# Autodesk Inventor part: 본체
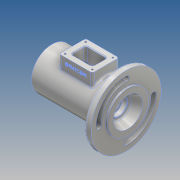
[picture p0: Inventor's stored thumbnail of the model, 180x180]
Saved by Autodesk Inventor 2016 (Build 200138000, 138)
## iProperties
Created: 2017-05
Part Number: 본체
Material: 알루미늄 6061
Document SubType Name: Modeling
Designer: Administrator
Mass: 680.072 g
Surface Area: 618.647 cm^2
Volume: 251.879 cm^3
Density: 2.7 g/cm^3
Appearance: 알루미늄 - 평지
Author: Administrator
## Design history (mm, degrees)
sketch "스케치1"
  geometry: L1 (57.5, 0)-(-57.5, 0); L2 (57.5, 0)-(57.5, 31); L3 (57.5, 31)-(-44.5, 31); L4 (-54.5, 31)-(-54.5, 53); L5 (-54.5, 53)-(-44.5, 53); L6 (-44.5, 53)-(-44.5, 31); L7 (-54.5, 31)-(-57.5, 31); L8 (-57.5, 31)-(-57.5, 0); 2 further points
  constraints: 16 end point, 5 perpendicular, 1 coincident, 1 horizontal, 1 midpoint, 1 point on line, 1 vertical
  dimensions: "d0" = 115 distance between parallel lines of L8 L2; "d2" = 62 diameter of L3 L1; "d4" = 13 distance between parallel lines of L8 L6; "d5" = 3 distance between parallel lines of L8 L4; "d6" = 106 diameter of L5 L1
revolve "회전1" sketch "스케치1" stored, may be unused: angle "d7" = 90 deg
sketch "스케치3"
  geometry: L1 (-57.5, 31)-(-57.5, -31) reference; L2 (57.5, 31)-(57.5, -31) reference; L3 (44.5, 31)-(-57.5, 31) reference; L4 (-26.5, -20)-(23.5, -20); L5 (23.5, -20)-(23.5, 20); L6 (23.5, 20)-(-26.5, 20); L7 (-26.5, 20)-(-26.5, -20); L8 (-26.5, -20)-(23.5, 20); L9 (23.5, -20)-(-26.5, 20); 3 further points
  constraints: 12 end point, 3 midpoint, 2 parallel, 1 horizontal, 1 horizontal alignment, 1 perpendicular
  dimensions: "d35" = 56 distance from line of point (-1.5, 0) L1; "d36" = 50 distance between parallel lines of L5 L7; "d37" = 40 distance between parallel lines of L4 L6
extrude "돌출1" join sketch "스케치3" distance "d38" = 44; taper "d39" = 0 deg
sketch "스케치2"
  geometry: L1 (57.5, 0)-(-57.5, 0); L2 (57.5, -31)-(57.5, 31) reference; L3 (-57.5, -31)-(-57.5, 31) reference; L4 (48.5, 0)-(48.5, 24); L5 (48.5, 24)-(45.5, 24); L6 (45.5, 24)-(45.5, 20); L7 (45.5, 20)-(36.5, 20); L8 (36.5, 20)-(36.5, 17.5); L9 (36.5, 17.5)-(33.25, 17.5); L10 (33.25, 17.5)-(33.25, 18.5); L11 (33.25, 18.5)-(31.5, 18.5); L12 (31.5, 18.5)-(31.5, 17.5); L13 (31.5, 17.5)-(20.5, 17.5); L14 (20.5, 17.5)-(20.5, 26); L15 (20.5, 26)-(-17.5, 26); L16 (-17.5, 26)-(-17.5, 17.5); L17 (-17.5, 17.5)-(-28.5, 17.5); L18 (-28.5, 17.5)-(-28.5, 16.5); L19 (-28.5, 16.5)-(-33.5, 16.5); L20 (-33.5, 16.5)-(-33.5, 10); L21 (-33.5, 10)-(-36.2, 10); L22 (-36.2, 10)-(-36.2, 12.5); L23 (-36.2, 12.5)-(-42.8, 12.5); L24 (-42.8, 12.5)-(-43.5, 12.904); L25 (-43.5, 12.904)-(-43.5, 16); L26 (-43.5, 16)-(-57.5, 22); 4 further points
  constraints: 48 end point, 15 perpendicular, 6 point on line, 5 midpoint, 3 vertical, 2 horizontal, 1 coincident
  dimensions: "d9" = 12 distance between parallel lines of L6 L2; "d10" = 3 distance between parallel lines of L6 L4; "d11" = 21 distance between parallel lines of L8 L2; "d12" = 26 distance between parallel lines of L12 L2; "d13" = 60 distance between parallel lines of L18 L12; "d14" = 38 distance between parallel lines of L16 L14; "d15" = 5 distance between parallel lines of L20 L18; "d16" = 14 distance from line of L3 L24.end; "d17" = 1.75 distance between parallel lines of L12 L10; "d18" = 48 diameter of L5 L1; "d19" = 40 diameter of L7 L1; "d20" = 35 diameter of L13 L1; "d21" = 37 diameter of L11 L1; "d22" = 52 diameter of L15 L1; "d23" = 33 diameter of L19 L1; "d27" = 44 diameter of L26.end L1; "d28" = 30 deg angle of L23 L24; "d29" = 32 diameter of L25.end L1; "d30" = 20 diameter of L21 L1; "d31" = 25 diameter of L23 L1; "d32" = 7.3 distance from line of L22 L24.end; "d33" = 0.7 horizontal distance of L24.end L23.end; "d40" = 56 distance from line of point (1.5, 26) L2
revolve "회전2" sketch "스케치2" stored, may be unused: angle "d34" = 90 deg
fillet "모깎기1" dims "d41" = 3
fillet "모깎기2" dims "d42" = 0.3
sketch "스케치4"
  geometry: L1 (-26.5, 20)-(-26.5, -20) reference; L2 (-17.5, -11)-(14.5, -11); L3 (14.5, -11)-(14.5, 11); L4 (14.5, 11)-(-17.5, 11); L5 (-17.5, 11)-(-17.5, -11); L6 (-17.5, -11)-(14.5, 11); L7 (14.5, -11)-(-17.5, 11); L8 (-57.5, 31)-(-57.5, -31) reference; 3 further points
  constraints: 12 end point, 3 midpoint, 2 parallel, 1 horizontal, 1 horizontal alignment, 1 perpendicular
  dimensions: "d43" = 56 distance from line of point (-1.5, 0) L8; "d44" = 32 distance between parallel lines of L3 L5; "d45" = 22 distance between parallel lines of L2 L4
extrude "돌출2" cut sketch "스케치4" distance "d46" = 44; taper "d47" = 0 deg
hole "구멍1" diameter "d50" = 40.376; stored, may be unused: countersink angle "d54" = 90 deg, drill point angle "d56" = 118 deg; dims "d48" = 10, "d49" = 10, "d51" = 84, "d52" = 4, "d53" = 2, "d55" = 9
sketch "스케치5"
  geometry: L1 (-22, 15.5)-(19, 15.5); L2 (19, 15.5)-(19, -15.5); L3 (19, -15.5)-(-22, -15.5); L4 (-22, -15.5)-(-22, 15.5); L5 (-22, 15.5)-(19, -15.5); L6 (19, 15.5)-(-22, -15.5); L7 (-57.5, 31)-(-57.5, -31) reference; 7 further points
  constraints: 12 end point, 4 coincident, 3 midpoint, 2 parallel, 1 horizontal, 1 horizontal alignment, 1 perpendicular
  dimensions: "d57" = 56 distance from line of L7 point (-1.5, 0); "d58" = 41 distance between parallel lines of L2 L4; "d59" = 31 distance between parallel lines of L3 L1
hole "구멍2" sketch "스케치5" at (-22, 15.5), (-22, -15.5), (19, -15.5), (19, 15.5) diameter "d60" = 2.459; stored, may be unused: countersink angle "d64" = 90 deg, drill point angle "d66" = 118 deg; dims "d61" = 6, "d62" = 4, "d63" = 2, "d65" = 8
chamfer "모따기1" distance "d67" = 1; stored, may be unused: second distance "d68" = 2, angle "d69" = 45 deg
fillet "모깎기3" dims "d70" = 3
fillet "모깎기4" dims "d71" = 3
fillet "모깎기5" dims "d72" = 3
chamfer "모따기2" distance "d73" = 1; stored, may be unused: second distance "d74" = 2, angle "d75" = 45 deg
fillet "모깎기6" dims "d76" = 3
sketch "스케치6"
  geometry: L1 (0, -60.51)-(0, 60.51); L2 (-63.255, 0)-(63.255, 0); C1 r 53 at (0, 0) reference; C2 r 31 at (0, 0) reference; A1 r 41.5 centre (0, 0) between (0, 41.5) and (41.5, 0); A2 r 4 centre (0, 41.5) between (0, 45.5) and (0, 37.5); A3 r 4 centre (41.5, 0) between (37.5, 0) and (45.5, 0); A4 r 4 centre (0, -41.5) between (0, -45.5) and (0, -37.5); A5 r 4 centre (-41.5, 0) between (-37.5, 0) and (-45.5, 0); A6 r 45.5 centre (0, 0) between (-45.5, 0) and (0, -45.5); A7 r 45.5 centre (0, 0) between (45.5, 0) and (0, 45.5); A8 r 37.5 centre (0, 0) between (-37.5, 0) and (0, -37.5); A9 r 37.5 centre (0, 0) between (37.5, 0) and (0, 37.5); 1 further point
  constraints: 20 point on circle, 9 centre point, 4 coincident, 4 end point, 4 point on line, 2 midpoint, 1 horizontal, 1 vertical
  dimensions: "d77" = 83 diameter of A1; "d78" = 8 diameter of A2; "d79" = 8 diameter of A3; "d80" = 8 diameter of A4; "d81" = 8 diameter of A5; "d84" = 37.5 radius of A8; "d85" = 45.5 radius of A6; "d86" = 37.5 radius of A9; "d87" = 45.5 radius of A7
extrude "돌출3" cut sketch "스케치6" distance "d88" = 20; taper "d89" = 0 deg
sketch "스케치7"
  geometry: L1 (0, 0)-(44, 0) reference; L2 (-34, -13)-(-34, -75) reference; 2 further points
  constraints: 1 other
  dimensions: "d90" = 56 distance from line of point (22, -8) L2; "d91" = 8 distance from line of point (22, -8) L1
feature "엠보싱1" sketch "스케치7" dims "d0" = 115, "d2" = 62, "d4" = 13, "d5" = 3, "d6" = 106, "d92" = 0.5, "d93" = 0
chamfer "모따기3" distance "d94" = 1; stored, may be unused: second distance "d95" = 2, angle "d96" = 45 deg
node "솔리드1"
other parameters: "d82" = 91, "d83" = 75
